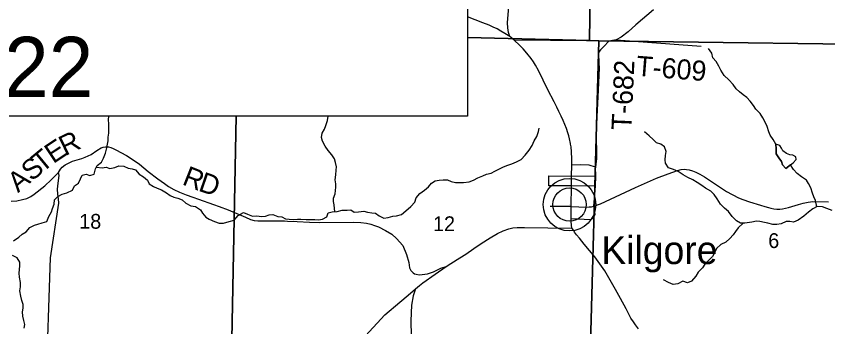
# Model space of a CAD drawing. Extents: x -20.5 to 34, y -66 to 23.9.
# Drawn here: x 3.275 to 5.573, y 16.645 to 17.524 of the extents above; entities that cross this region are included whole.
import ezdxf

# ---------------------------------------------------------------- set-up
doc = ezdxf.new("R2010")
doc.units = 0
for name, color, linetype in [('GM_X_County_Road', 7, 'Continuous'), ('GM_X_County_Text', 7, 'Continuous'), ('GM_X_Major_River', 7, 'Continuous'), ('GM_X_Minor_Lake', 7, 'Continuous'), ('GM_X_Minor_River', 7, 'Continuous'), ('GM_X_Minor_River_Text', 7, 'Continuous'), ('GM_X_Section_Text', 7, 'Continuous'), ('GM_X_State_Route', 7, 'Continuous'), ('GM_X_State_Shield', 7, 'Continuous'), ('GM_X_Township_Road', 7, 'Continuous'), ('GM_X_Township_Road_Text', 7, 'Continuous'), ('GM_X_Township_Text', 7, 'Continuous'), ('SH_Text', 7, 'Continuous')]:
    doc.layers.add(name, color=color, linetype=linetype)

msp = doc.modelspace()

# ---------------------------------------------------------------- linework, layer by layer
at = {"layer": 'GM_X_County_Road'}
for radius in [0.0744, 0.0472]:
    msp.add_circle((4.8414, 16.9908), radius, dxfattribs=at)
at = {"layer": 'GM_X_County_Text'}
for p, q in [((4.9734, 17.4571), (5.2142, 17.4396)), ((4.8474, 17.0718), (4.9159, 17.0727)), ((4.8463, 16.9854), (4.7865, 16.9856))]:
    msp.add_line(p, q, dxfattribs=at)
for points in [[(4.9529, 17.4534), (4.9386, 17.4387), (4.9295, 17.4294), (4.9257, 17.4246), (4.923, 17.4184), (4.9232, 17.409), (4.9241, 17.4005), (4.9247, 17.3914), (4.9257, 17.3767), (4.9228, 17.3159), (4.9188, 17.2395), (4.917, 17.1955), (4.9174, 17.1214), (4.9153, 17.0964)], [(4.9153, 17.0964), (4.8965, 17.1022), (4.872, 17.1034), (4.8481, 17.1023)], [(3.2635, 16.3144), (3.2839, 16.3283), (3.3288, 16.3487), (3.3542, 16.3609), (3.3599, 16.3637), (3.3646, 16.3694), (3.3636, 16.3694), (3.3655, 16.3713), (3.3663, 16.3761), (3.3602, 16.4143), (3.3594, 16.4735), (3.3718, 16.8405), (3.3957, 16.9949), (3.3943, 17.0069), (3.3923, 17.02), (3.3913, 17.0343), (3.3936, 17.0515), (3.396, 17.073), (3.3943, 17.0819)], [(4.9104, 16.9862), (4.9147, 17.0429), (4.9159, 17.0727), (4.9153, 17.0964)], [(4.8159, 17.0443), (4.8149, 17.0443), (4.7823, 17.0438), (4.7829, 17.0723), (4.8474, 17.0718)], [(4.9147, 17.0429), (4.8472, 17.0444), (4.8159, 17.0443)], [(4.8457, 16.951), (4.9011, 16.9487), (4.9061, 16.9515), (4.9099, 16.955), (4.9125, 16.9588), (4.9138, 16.9633), (4.9104, 16.9862)]]:
    msp.add_lwpolyline(points, dxfattribs=at)
at = {"layer": 'GM_X_Major_River'}
msp.add_line((4.8414, 16.9908), (4.8414, 16.9908), dxfattribs=at)
at = {"layer": 'GM_X_Minor_Lake'}
for points in [[(3.8907, 18.0245), (3.8987, 18.493), (4.9118, 18.4742), (4.898, 17.4556), (4.5524, 17.4637)], [(4.5524, 17.4637), (4.898, 17.4556), (4.9246, 17.4548), (4.8948, 16.3916), (3.8817, 16.4153), (3.8974, 17.2409)], [(3.8974, 17.2409), (3.8817, 16.4153), (2.8609, 16.4392), (2.8718, 17.2409)]]:
    msp.add_lwpolyline(points, dxfattribs=at)
for points in [[(4.9118, 18.4742), (5.9332, 18.4574), (5.9313, 18.3709), (5.9103, 17.4412), (4.9246, 17.4548), (4.898, 17.4556)], [(4.9246, 17.4548), (5.9103, 17.4412), (5.9082, 17.3615), (5.9397, 17.3613), (5.9209, 16.3687), (4.8948, 16.3916)]]:
    msp.add_lwpolyline(points, close=True, dxfattribs=at)
at = {"layer": 'GM_X_Minor_River'}
for points in [[(5.4256, 17.1619), (5.4266, 17.149), (5.4268, 17.135), (5.4341, 17.123), (5.4415, 17.1132), (5.4447, 17.103), (5.4543, 17.0933), (5.467, 17.1038)], [(5.467, 17.1038), (5.4745, 17.1088), (5.4827, 17.1184), (5.4822, 17.1264), (5.4734, 17.1308), (5.4647, 17.1322), (5.4559, 17.1354), (5.4456, 17.1429), (5.4413, 17.1508), (5.4366, 17.1583), (5.4256, 17.1619)]]:
    msp.add_lwpolyline(points, dxfattribs=at)
at = {"layer": 'GM_X_Minor_River_Text'}
for points in [[(5.5418, 16.9847), (5.5374, 17.002), (5.5335, 17.013), (5.5295, 17.0228), (5.5244, 17.0382), (5.5177, 17.0503), (5.5119, 17.0604), (5.4985, 17.069), (5.4855, 17.0786), (5.4751, 17.0906), (5.467, 17.1038), (5.4543, 17.0933), (5.4447, 17.103), (5.4415, 17.1132), (5.4341, 17.123), (5.4268, 17.135), (5.4266, 17.149), (5.4256, 17.1619), (5.4175, 17.1751), (5.4093, 17.1875), (5.4054, 17.1973), (5.4006, 17.2116), (5.3951, 17.2244), (5.3889, 17.2365), (5.3808, 17.2489), (5.3688, 17.2612), (5.3626, 17.271), (5.353, 17.2841), (5.343, 17.2938), (5.3334, 17.302), (5.3231, 17.3102), (5.3131, 17.3191), (5.305, 17.3308), (5.2923, 17.3446), (5.2788, 17.3565), (5.2695, 17.3712), (5.2644, 17.3832), (5.2563, 17.396), (5.247, 17.4065), (5.2442, 17.4194), (5.2345, 17.4329)], [(3.4567, 17.0642), (3.461, 17.0742), (3.4727, 17.077), (3.483, 17.073), (3.4958, 17.0774), (3.499, 17.0919), (3.5041, 17.1014), (3.516, 17.1111), (3.5219, 17.1226), (3.5277, 17.1363), (3.5309, 17.1516), (3.5333, 17.1618), (3.5347, 17.1713), (3.5353, 17.1816), (3.5366, 17.1933), (3.5371, 17.2074), (3.5369, 17.2195), (3.5363, 17.2309), (3.5367, 17.2409)], [(4.1771, 16.9708), (4.1753, 16.9897), (4.1728, 16.9995), (4.1734, 17.0094), (4.1774, 17.0212), (4.1787, 17.0307), (4.1797, 17.0402), (4.1795, 17.0497), (4.1778, 17.0607), (4.1798, 17.0755), (4.1804, 17.088), (4.1817, 17.0975), (4.1789, 17.11), (4.176, 17.1205), (4.1679, 17.1314), (4.1582, 17.1437), (4.1493, 17.1561), (4.1415, 17.1707), (4.1391, 17.1805), (4.1411, 17.1935), (4.1474, 17.2042), (4.1517, 17.2145), (4.1556, 17.2286), (4.1584, 17.2409)], [(4.6782, 17.106), (4.691, 17.1115), (4.7041, 17.1189), (4.7153, 17.1309), (4.7268, 17.1451), (4.736, 17.1578), (4.7414, 17.1715), (4.7484, 17.1834), (4.7535, 17.1979), (4.7556, 17.2074)], [(5.5851, 16.9743), (5.5703, 16.9794), (5.5573, 16.9849), (5.543, 16.9854), (5.5306, 16.9784), (5.5182, 16.9691), (5.5048, 16.9579), (5.4883, 16.9463), (5.4751, 16.9415), (5.4653, 16.9425), (5.4547, 16.9431), (5.4408, 16.9368), (5.4279, 16.934), (5.4174, 16.9342), (5.4029, 16.9378), (5.3934, 16.9403), (5.3801, 16.9431), (5.3707, 16.9441), (5.3578, 16.9409), (5.3382, 16.9383), (5.3253, 16.9385), (5.3146, 16.9444), (5.3023, 16.9575), (5.2919, 16.971), (5.2797, 16.9803), (5.2693, 16.9919), (5.2596, 17.0069), (5.2507, 17.0193), (5.2411, 17.0286), (5.2266, 17.0371), (5.2162, 17.0453), (5.2032, 17.0535), (5.1906, 17.0608), (5.1765, 17.0678), (5.1632, 17.0752), (5.1494, 17.0849), (5.1353, 17.09), (5.1216, 17.0947), (5.1127, 17.1078), (5.1126, 17.1173), (5.1135, 17.1298), (5.1152, 17.1416), (5.1101, 17.1544), (5.1002, 17.1615), (5.088, 17.1662), (5.0784, 17.1748), (5.0669, 17.1857), (5.0539, 17.1968)], [(3.5016, 17.0968), (3.5178, 17.0945), (3.5295, 17.0969), (3.5398, 17.0933), (3.5534, 17.0958), (3.5654, 17.1006), (3.5791, 17.0997), (3.5917, 17.0942), (3.6031, 17.0921), (3.6126, 17.0893), (3.623, 17.0773), (3.6352, 17.0696), (3.6464, 17.0603), (3.6515, 17.0501), (3.6637, 17.042), (3.674, 17.0372), (3.6862, 17.0325), (3.7, 17.0244), (3.7103, 17.0166), (3.7214, 17.0115), (3.732, 17.0094), (3.7446, 17.0047), (3.755, 16.995), (3.7691, 16.9873), (3.782, 16.9853), (3.7962, 16.976), (3.8024, 16.9663), (3.8113, 16.9555), (3.8209, 16.9499), (3.8362, 16.9426), (3.8495, 16.9383), (3.862, 16.9385), (3.8774, 16.9426), (3.8913, 16.947), (3.9028, 16.9604), (3.9182, 16.9687), (3.9297, 16.9635), (3.9438, 16.9577), (3.9562, 16.9594), (3.9688, 16.9574), (3.9805, 16.9576), (3.9907, 16.9616), (4.0016, 16.9625), (4.015, 16.957), (4.0267, 16.9561), (4.0374, 16.9506), (4.0473, 16.95), (4.0601, 16.9487), (4.0707, 16.9493), (4.0809, 16.9498), (4.0953, 16.9486), (4.1059, 16.9491), (4.12, 16.9482), (4.1302, 16.948), (4.1415, 16.9494), (4.1543, 16.9564), (4.1575, 16.9678), (4.1695, 16.9707), (4.1832, 16.9709), (4.1975, 16.9746), (4.2115, 16.9748), (4.2217, 16.9757), (4.2316, 16.9698), (4.2441, 16.9704), (4.2585, 16.9722), (4.2695, 16.9694), (4.2813, 16.9673), (4.2919, 16.9663), (4.3022, 16.9589), (4.3152, 16.9527), (4.328, 16.9544), (4.3412, 16.9585), (4.3514, 16.959), (4.3658, 16.963), (4.3781, 16.9735), (4.3922, 16.9851), (4.403, 16.9974), (4.407, 17.01), (4.4177, 17.0227), (4.4308, 17.0313), (4.4424, 17.0409), (4.4509, 17.0513), (4.461, 17.0579), (4.472, 17.0604), (4.4837, 17.0613), (4.4954, 17.0608), (4.5061, 17.0564), (4.5186, 17.0536), (4.5285, 17.053), (4.541, 17.0536), (4.5568, 17.0554), (4.5692, 17.0602), (4.582, 17.0668), (4.5959, 17.0727), (4.6064, 17.0771), (4.6192, 17.0803), (4.6298, 17.0855), (4.6448, 17.0933), (4.6545, 17.0976), (4.6669, 17.1024), (4.6782, 17.106)], [(3.267, 16.8885), (3.2816, 16.899), (3.2917, 16.9075), (3.3025, 16.9138), (3.3129, 16.9261), (3.3261, 16.9327), (3.3358, 16.9356), (3.3479, 16.9392), (3.3615, 16.9432), (3.3673, 16.9573), (3.375, 16.97), (3.3775, 16.9795), (3.3822, 16.9925), (3.3831, 17.0046), (3.3924, 17.0142), (3.4048, 17.0205), (3.4184, 17.0238), (3.4338, 17.0316), (3.4392, 17.0435), (3.4508, 17.0512), (3.4567, 17.0642)], [(5.3326, 16.9384), (5.3187, 16.9247), (5.3117, 16.9148), (5.3043, 16.9052), (5.2957, 16.8944), (5.2838, 16.884), (5.2695, 16.8777), (5.2579, 16.8669), (5.2532, 16.8562), (5.2466, 16.8436), (5.2335, 16.832), (5.2246, 16.822), (5.2179, 16.8117), (5.206, 16.7993), (5.1986, 16.7878), (5.1871, 16.7744), (5.175, 16.7689), (5.1625, 16.7736), (5.1482, 16.7662), (5.135, 16.7645), (5.1213, 16.7704), (5.1079, 16.7781)], [(3.297, 16.6411), (3.2987, 16.6517), (3.2966, 16.6623), (3.293, 16.6748), (3.2924, 16.6873), (3.2941, 16.6971), (3.2939, 16.7081), (3.2907, 16.7195), (3.2879, 16.7319), (3.2846, 16.7466), (3.2867, 16.7577), (3.2864, 16.7702), (3.2843, 16.7857), (3.2833, 16.7963), (3.2839, 16.8069), (3.2853, 16.8176), (3.2851, 16.8278), (3.2773, 16.8402), (3.2639, 16.8464)]]:
    msp.add_lwpolyline(points, dxfattribs=at)
at = {"layer": 'GM_X_State_Route'}
for points in [[(4.6722, 17.4669), (4.6684, 17.4785), (4.6666, 17.4911), (4.6657, 17.5056), (4.673, 17.5988)], [(5.0796, 17.5421), (5.0291, 17.5001), (5.0071, 17.4796), (4.9878, 17.4647), (4.9734, 17.4571), (4.9529, 17.4534), (4.9274, 17.4535), (4.8892, 17.4543), (4.6849, 17.4561)], [(3.2607, 17.0004), (3.2766, 17.0016), (3.2925, 17.0052), (3.3046, 17.0084), (3.3157, 17.0138), (3.3256, 17.0208), (3.3553, 17.0435), (3.3733, 17.0605), (3.3943, 17.0819), (3.3998, 17.0911), (3.4043, 17.0967), (3.4129, 17.1031), (3.434, 17.1137), (3.4605, 17.1213), (3.4703, 17.125), (3.487, 17.1331), (3.5032, 17.144), (3.5152, 17.1516), (3.5211, 17.1536), (3.5277, 17.1544), (3.5362, 17.154), (3.5425, 17.1522), (3.5493, 17.1494), (3.5569, 17.1457), (3.5873, 17.1298), (3.603, 17.1194), (3.6237, 17.1049), (3.648, 17.0846), (3.6753, 17.0641), (3.6941, 17.0503), (3.7063, 17.0422), (3.7207, 17.0335), (3.7366, 17.0258), (3.7557, 17.0185), (3.7746, 17.0118), (3.791, 17.0066), (3.8335, 16.9907), (3.8495, 16.9852), (3.875, 16.9761), (3.9241, 16.9552), (3.938, 16.9487), (3.9485, 16.9459), (3.9587, 16.9452), (4.0341, 16.9448), (4.0424, 16.9441), (4.0697, 16.9431), (4.1054, 16.9407), (4.1342, 16.9399), (4.2309, 16.9409), (4.2505, 16.94), (4.2669, 16.9379), (4.2786, 16.9354), (4.2892, 16.932), (4.3, 16.9274), (4.3203, 16.9171), (4.338, 16.9072), (4.3516, 16.8948), (4.3692, 16.875), (4.3799, 16.8495), (4.386, 16.8265), (4.388, 16.812), (4.3924, 16.8045), (4.3982, 16.7978), (4.4024, 16.7948), (4.4073, 16.7934), (4.4152, 16.7924), (4.4243, 16.7927), (4.4392, 16.7952), (4.4562, 16.8003), (4.4771, 16.8104), (4.4916, 16.8151)], [(4.4049, 16.7521), (4.3984, 16.7329), (4.3937, 16.7064), (4.3925, 16.6839), (4.3922, 16.6604), (4.393, 16.62)]]:
    msp.add_lwpolyline(points, dxfattribs=at)
at = {"layer": 'GM_X_Township_Road'}
for p, q in [((4.8457, 16.951), (4.8463, 16.9854)), ((4.8463, 16.942), (4.8457, 16.951)), ((4.8475, 16.9241), (4.8463, 16.942))]:
    msp.add_line(p, q, dxfattribs=at)
for points in [[(4.8445, 17.1616), (4.8442, 17.1635), (4.8412, 17.1771), (4.8391, 17.186), (4.8367, 17.1944), (4.8328, 17.2061), (4.8285, 17.2175), (4.8233, 17.2293), (4.8177, 17.241), (4.811, 17.2547), (4.805, 17.2671), (4.7975, 17.2817), (4.7804, 17.3157), (4.7535, 17.3707), (4.7453, 17.3855), (4.7391, 17.3954), (4.7328, 17.4046), (4.7206, 17.4201), (4.7105, 17.4315), (4.6998, 17.4425), (4.6849, 17.4561), (4.6722, 17.4669), (4.6579, 17.4757), (4.6472, 17.482), (4.636, 17.4883), (4.6252, 17.4935), (4.6136, 17.4986), (4.596, 17.5059), (4.5524, 17.5224)], [(4.8463, 16.9854), (4.8472, 17.0444), (4.8474, 17.0718), (4.8481, 17.1023), (4.8482, 17.12), (4.8473, 17.1407), (4.8457, 17.1543), (4.8445, 17.1616)], [(4.8463, 16.9854), (4.889, 16.9839), (4.897, 16.9843), (4.9039, 16.9849), (4.9104, 16.9862), (4.929, 16.9933), (5.0284, 17.0394), (5.088, 17.0654), (5.1211, 17.0784), (5.1473, 17.0873), (5.1576, 17.0904), (5.1659, 17.0908), (5.173, 17.0905), (5.1805, 17.0889), (5.1894, 17.0865), (5.1987, 17.0828), (5.2102, 17.0773), (5.2238, 17.0692), (5.2859, 17.0282), (5.3198, 17.0099), (5.3318, 17.0052), (5.3506, 16.9988), (5.3824, 16.9891), (5.394, 16.9859), (5.4049, 16.9823), (5.4114, 16.9803), (5.4203, 16.979), (5.4284, 16.9783), (5.4368, 16.9782), (5.4448, 16.9793), (5.4612, 16.9822), (5.4896, 16.9909), (5.5027, 16.9946), (5.5172, 16.9975), (5.5301, 16.9996), (5.5745, 16.9987)], [(4.1972, 16.547), (4.318, 16.6789), (4.3608, 16.7145), (4.3846, 16.7345), (4.4049, 16.7521), (4.4165, 16.7616), (4.4264, 16.7692), (4.4613, 16.7935), (4.4916, 16.8151), (4.5053, 16.8241), (4.5308, 16.8398), (4.5479, 16.8508), (4.5705, 16.8664), (4.5916, 16.8805), (4.6164, 16.8967), (4.6377, 16.9089), (4.6539, 16.9167), (4.6691, 16.9223), (4.6806, 16.9251), (4.693, 16.9264), (4.7137, 16.9263), (4.7801, 16.9248), (4.8475, 16.9241)], [(5.0368, 16.6388), (5.0282, 16.65), (5.0221, 16.6593), (5.0154, 16.6696), (5.0079, 16.6826), (5.0016, 16.6954), (4.9861, 16.7251), (4.972, 16.7502), (4.9414, 16.803), (4.913, 16.8432), (4.8831, 16.879), (4.8697, 16.8954), (4.8613, 16.9056), (4.8584, 16.9094), (4.8559, 16.913), (4.8531, 16.9172), (4.8475, 16.9241)]]:
    msp.add_lwpolyline(points, dxfattribs=at)
at = {"layer": 'SH_Text'}
msp.add_lwpolyline([(2.3813, 18.0245), (4.5524, 18.0245), (4.5524, 17.2409), (2.3813, 17.2409)], close=True, dxfattribs=at)

# ---------------------------------------------------------------- texts
at = {"layer": 'GM_X_Section_Text'}
for s, rotation, p in [('T-682', 87.4983, (5.0166, 17.2005)), ('T-609', 355.5152, (5.0288, 17.3558))]:
    msp.add_text(s, height=0.05682, rotation=rotation, dxfattribs=at).set_placement(p)
at = {"layer": 'GM_X_State_Shield'}
msp.add_text('Kilgore', height=0.07898, rotation=0, dxfattribs=at).set_placement((4.9315, 16.8224))
at = {"layer": 'GM_X_Township_Road_Text'}
for s, rotation, p in [('R', 25.8022, (3.4131, 17.1278)), ('E', 33.5355, (3.3794, 17.1053)), ('T', 39.4549, (3.3478, 17.0792)), ('S', 39.544, (3.3183, 17.0549)), ('R', 338.4947, (3.7419, 17.0488)), ('A', 39.5476, (3.2797, 17.023)), ('D', 341.0248, (3.7878, 17.0308))]:
    msp.add_text(s, height=0.0568, rotation=rotation, dxfattribs=at).set_placement(p)
at = {"layer": 'GM_X_Township_Text'}
for s, height, p in [('18', 0.04186, (3.4531, 16.9225)), ('12', 0.04186, (4.4548, 16.9157)), ('6', 0.0419, (5.404, 16.8679))]:
    msp.add_text(s, height=height, rotation=0, dxfattribs=at).set_placement(p)
at = {"layer": 'SH_Text'}
msp.add_text('SLM 10.22', height=0.17, dxfattribs=at).set_placement((2.3937, 17.2959))

doc.saveas('drawing.dxf')
